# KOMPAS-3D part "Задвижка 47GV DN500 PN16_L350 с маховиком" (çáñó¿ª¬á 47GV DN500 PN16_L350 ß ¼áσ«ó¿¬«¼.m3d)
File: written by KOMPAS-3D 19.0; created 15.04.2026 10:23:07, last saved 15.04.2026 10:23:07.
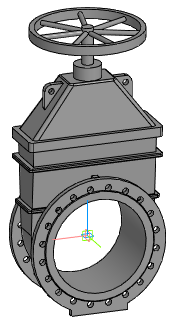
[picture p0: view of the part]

Document properties: Автор: Евгений; Полное имя файла: Z:\3.Личные\kachalov\3d для проектировщиков\2.1 Тип 47GV, 47GV.Z\Задвижка 47GV_DN40-DN600\stp_Задвижка 47GV\Задвижка 47GV DN500 PN16_L350 с маховиком.m3d

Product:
- Part/product: Задвижка 47GV DN500 PN16_L350 с маховиком

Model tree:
1. Операция без истории:1  (labels: Задвижка 47GV DN500 PN16_L350 с маховиком)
